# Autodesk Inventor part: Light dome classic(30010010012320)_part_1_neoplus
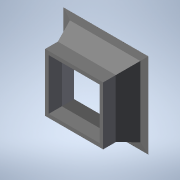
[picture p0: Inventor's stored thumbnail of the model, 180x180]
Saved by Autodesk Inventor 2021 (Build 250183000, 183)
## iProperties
Created: 2026-04
Part Number: Light dome classic(30010010012320)_part_1_neoplus
Material: Generic
Catalog Web Link: www.3dfindit.com
Description: Light dome classic_part_1_neoplus-
Vendor: KINGSPAN
Document SubType Name: Modeling
Designer: psAdmin
Manufacturer: KINGSPAN
Mass: 110789 g
Surface Area: 53147.3 cm^2
Volume: 110789 cm^3
Density: 1 g/cm^3
Appearance: PSOLRGB-255-255-255
Category: PARTsolutions
Company: KINGSPAN
Title: Light dome classic(30010010012320)_part_1_neoplus
Author: Cadenas PARTsolutions
PSOL_IDENT_0: {$CADENAS_DATA/23d-libs/kingspan_kla/light_dome_classic_neoplus/parts/part_1.prj},297 {VTYP=3D},{NB=
PSOL_IDENT_1: Light dome classic(30010010012320)_part_1_neoplus},{LINA=Light dome classic(30010010012320)_part_1_n
PSOL_IDENT_2: eoplus},{NN=Light dome classic_part_1_neoplus},{DATE=20.03.2025 09:30:52},{GEOMDATE=03.07.2024 07:48
PSOL_IDENT_3: :00},{VERSION=},{LINEID=10},{WBVAR=LODLEVEL,L,W,DP,OP,BA,INS,RT},{WBNUMERIC=W,RT}  {NB=Light dome cl
PSOL_IDENT_4: assic(30010010012320)_part_1_neoplus},{LINA=Light dome classic(30010010012320)_part_1_neoplus},{KT=D
PSOL_IDENT_5: UMMY},{IDNR=},{PN=Light dome classic},{LODLEVEL=300},{L=100},{W=100},{DRIVE=1},{WX=100,150,200,250,3
PSOL_IDENT_6: 00},{DP=1},{OP=2},{BA=3},{INS=2},{INSX='2','without insulation'},{OPX='1','manualy','2','Linear driv
PSOL_IDENT_7: e 300 mm stroke 24 V and 230 V','3','Linear drive 500 mm stroke 24 V and 230 V','4','Linear drive 75
PSOL_IDENT_8: 0 mm stroke 24 V and 230 V'},{LX=1000},{XWX=1000},{HEI=1048.274},{BAX='1', 'PVC base 15 cm','2', 'PV
PSOL_IDENT_9: C base 30 cm', '3', 'PVC base 50 cm' , '4', 'Metal base single skin (steel), 30 cm', '5' , 'Metal ba
PSOL_IDENT_10: se single skin (steel), 40 cm', '6' , 'Metal base single skin (steel), 50 cm', '7' , 'Metal base dou
PSOL_IDENT_11: ble skin (aluminum), 30 cm', '8' , 'Metal base double skin (aluminum), 40 cm', '9' , 'Metal base dou
PSOL_IDENT_12: ble skin (aluminum), 50 cm', '10', 'Steel base 30 cm', '11' , 'Steel base 40 cm', '12', 'Steel base
PSOL_IDENT_13: 50 cm', '13' , 'AK30 AL/AL', '14' , 'AK40 AL/AL', '15' , 'AK50 AL/AL', '16' , 'AK50 ST-TG'},{RT=0}
NB: Light dome classic(30010010012320)_part_1_neoplus
NN: Light dome classic_part_1_neoplus
NBSYN: $PN.($LODLEVEL.$L.$W.$DP.$OP.$BA.$INS.$RT.)_part_1_neoplus
LINA: Light dome classic(30010010012320)_part_1_neoplus
CATALOG: Light + Air
PN: Light dome classic
LODLEVEL: 300
L: 100
W: 100
DP: Natural ventilation
OP: Linear drive 300 mm stroke 24 V and 230 V
BA: PVC base 50 cm
INS: without insulation
RT: 0
SUPPLIER: KINGSPAN
ARTICLENO: Light dome classic(30010010012320)_part_1_neoplus
BOMINFO: Light dome classic(30010010012320)_part_1_neoplus
CREATOR: CADENAS GmbH
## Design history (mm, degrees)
sketch "Sketch_1"
  geometry: L1 (-400.529, 500)-(-457.495, 500); L2 (-457.495, 500)-(-457.495, 300); L3 (-457.495, 300)-(-555.041, 12.062); L4 (-555.041, 12.062)-(-670.088, 1.996); L5 (-670.001, 0)-(-500, 0); L6 (-500, 0)-(-400.529, 293.622); L7 (-400.529, 293.622)-(-400.529, 500); A1 r 1 centre (-670.001, 1) between (-670.088, 1.996) and (-670.001, 0)
  constraints: 14 end point, 2 point on circle, 1 centre point
extrude "Extrusion1" join sketch "Sketch_1" stored distance "d0" = 2000; taper "d1" = 0 deg
sketch "Sketch_2"
  geometry: L1 (400.529, 500)-(400.529, 293.622); L2 (400.529, 293.622)-(500, 0); L3 (500, 0)-(670.001, 0); L4 (670.088, 1.996)-(555.041, 12.062); L5 (555.041, 12.062)-(457.495, 300); L6 (457.495, 300)-(457.495, 500); L7 (457.495, 500)-(400.529, 500); A1 r 1 centre (670.001, 1) between (670.001, 0) and (670.088, 1.996)
  constraints: 14 end point, 2 point on circle, 1 centre point
extrude "Extrusion2" join sketch "Sketch_2" stored distance "d2" = 2000; taper "d3" = 0 deg
sketch "Sketch_3"
  geometry: L1 (670.088, 1.996)-(555.041, 12.062); L2 (555.041, 12.062)-(457.495, 300); L3 (457.495, 300)-(457.495, 500); L4 (457.495, 500)-(400.529, 500); L5 (400.529, 500)-(400.529, 293.622); L6 (400.529, 293.622)-(500, 0); L7 (500, 0)-(670.001, 0); A1 r 1 centre (670.001, 1) between (670.001, 0) and (670.088, 1.996)
  constraints: 14 end point, 2 point on circle, 1 centre point
extrude "Extrusion3" join sketch "Sketch_3" stored distance "d4" = 2000; taper "d5" = 0 deg
sketch "Sketch_4"
  geometry: L1 (-400.529, 500)-(-457.495, 500); L2 (-457.495, 500)-(-457.495, 300); L3 (-457.495, 300)-(-555.041, 12.062); L4 (-555.041, 12.062)-(-670.088, 1.996); L5 (-670.001, 0)-(-500, 0); L6 (-500, 0)-(-400.529, 293.622); L7 (-400.529, 293.622)-(-400.529, 500); A1 r 1 centre (-670.001, 1) between (-670.088, 1.996) and (-670.001, 0)
  constraints: 14 end point, 2 point on circle, 1 centre point
extrude "Extrusion4" join sketch "Sketch_4" stored distance "d6" = 2000; taper "d7" = 0 deg
sketch "Sketch_5"
  geometry: L1 (-400, 600)-(-1000, 600); L2 (-1000, 600)-(-1000, -30); L3 (-1000, -30)-(-569.29, -30); L4 (-569.29, -30)-(-559.127, 0); L5 (-559.127, 0)-(-670.001, 0); L6 (-670.088, 1.996)-(-555.041, 12.062); L7 (-555.041, 12.062)-(-457.495, 300); L8 (-457.495, 300)-(-457.495, 500); L9 (-457.495, 500)-(-400, 500); L10 (-400, 500)-(-400, 600); A1 r 1 centre (-670.001, 1) between (-670.088, 1.996) and (-670.001, 0)
  constraints: 20 end point, 2 point on circle, 1 centre point
extrude "Extrusion5" cut sketch "Sketch_5" stored distance "d8" = 2000; taper "d9" = 0 deg
sketch "Sketch_6"
  geometry: L1 (1000, -30)-(1000, 600); L2 (1000, 600)-(400, 600); L3 (400, 600)-(400, 500); L4 (400, 500)-(457.495, 500); L5 (457.495, 500)-(457.495, 300); L6 (457.495, 300)-(555.041, 12.062); L7 (555.041, 12.062)-(670.088, 1.996); L8 (670.001, 0)-(559.127, 0); L9 (559.127, 0)-(569.29, -30); L10 (569.29, -30)-(1000, -30); A1 r 1 centre (670.001, 1) between (670.001, 0) and (670.088, 1.996)
  constraints: 20 end point, 2 point on circle, 1 centre point
extrude "Extrusion6" cut sketch "Sketch_6" stored distance "d10" = 2000; taper "d11" = 0 deg
sketch "Sketch_7"
  geometry: L1 (1000, 600)-(400, 600); L2 (400, 600)-(400, 500); L3 (400, 500)-(457.495, 500); L4 (457.495, 500)-(457.495, 300); L5 (457.495, 300)-(555.041, 12.062); L6 (555.041, 12.062)-(670.088, 1.996); L7 (670.001, 0)-(559.127, 0); L8 (559.127, 0)-(569.29, -30); L9 (569.29, -30)-(1000, -30); L10 (1000, -30)-(1000, 600); A1 r 1 centre (670.001, 1) between (670.001, 0) and (670.088, 1.996)
  constraints: 20 end point, 2 point on circle, 1 centre point
extrude "Extrusion7" cut sketch "Sketch_7" stored distance "d12" = 2000; taper "d13" = 0 deg
sketch "Sketch_9"
  geometry: L1 (-1000, 600)-(-1000, -30); L2 (-1000, -30)-(-569.29, -30); L3 (-569.29, -30)-(-559.127, 0); L4 (-559.127, 0)-(-670.001, 0); L5 (-670.088, 1.996)-(-555.041, 12.062); L6 (-555.041, 12.062)-(-457.495, 300); L7 (-457.495, 300)-(-457.495, 500); L8 (-457.495, 500)-(-400, 500); L9 (-400, 500)-(-400, 600); L10 (-400, 600)-(-1000, 600); A1 r 1 centre (-670.001, 1) between (-670.088, 1.996) and (-670.001, 0)
  constraints: 20 end point, 2 point on circle, 1 centre point
extrude "Extrusion8" cut sketch "Sketch_9" stored distance "d14" = 2000; taper "d15" = 0 deg
node "1_XY"
node "1_YZ"
node "1_ZX"
node "1_X"
node "1_Y"
node "1_Z"
node "1_Center"
node "IP_for_dummy_XY"
node "IP_for_dummy_YZ"
node "IP_for_dummy_ZX"
node "IP_for_dummy_X"
node "IP_for_dummy_Y"
node "IP_for_dummy_Z"
node "IP_for_dummy_Center"
node "IP_for_part_10_1_XY"
node "IP_for_part_10_1_YZ"
node "IP_for_part_10_1_ZX"
node "IP_for_part_10_1_X"
node "IP_for_part_10_1_Y"
node "IP_for_part_10_1_Z"
node "IP_for_part_10_1_Center"
node "IP_for_part_2_XY"
node "IP_for_part_2_YZ"
node "IP_for_part_2_ZX"
node "IP_for_part_2_X"
node "IP_for_part_2_Y"
node "IP_for_part_2_Z"
node "IP_for_part_2_Center"
node "light_dome_classic_XY"
node "light_dome_classic_YZ"
node "light_dome_classic_ZX"
node "light_dome_classic_X"
node "light_dome_classic_Y"
node "light_dome_classic_Z"
node "light_dome_classic_Center"
body "Solid1"
other parameters: "d16" = 0, "d17" = 0, "d18" = 0, "d19" = 0
